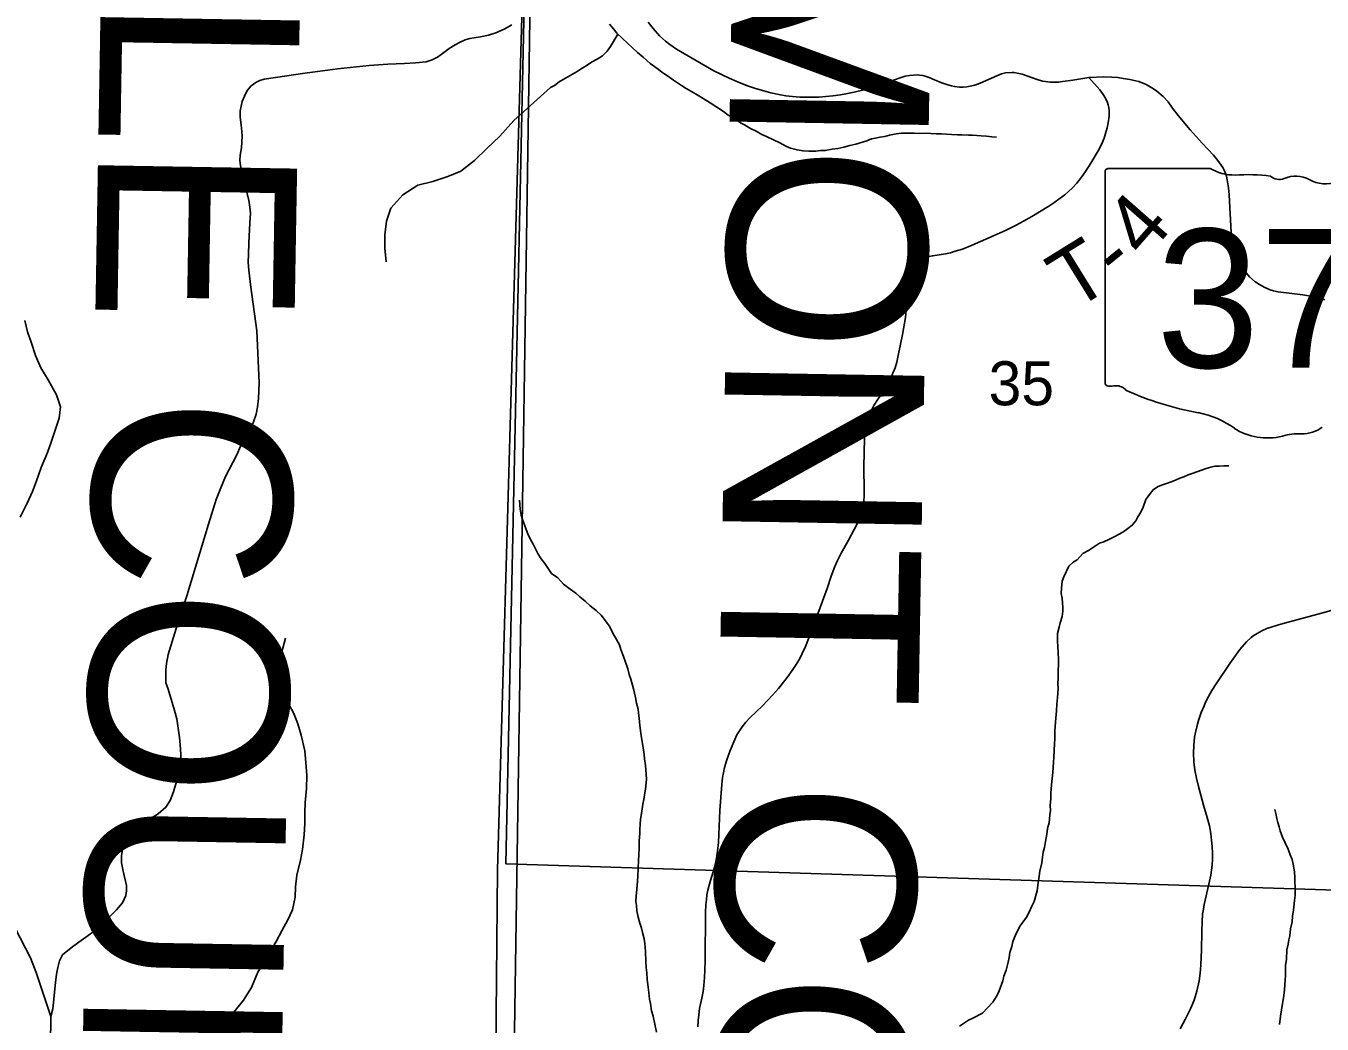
# Model space of a CAD drawing. Extents: x 0 to 34, y 0 to 22.
# Drawn here: x 26.601 to 27.832, y 18.434 to 19.383 of the extents above; entities that cross this region are included whole.
import ezdxf

# ---------------------------------------------------------------- set-up
doc = ezdxf.new("R2010")
doc.units = 0
for name, color, linetype in [('GM_X_Corporation', 7, 'Continuous'), ('GM_X_County', 7, 'Continuous'), ('GM_X_County_Text', 7, 'Continuous'), ('GM_X_Minor_River', 7, 'Continuous'), ('GM_X_Section_Text', 7, 'Continuous'), ('GM_X_State_Route', 7, 'Continuous'), ('GM_X_State_Shield', 7, 'Continuous'), ('GM_X_Township_Road', 7, 'Continuous'), ('GM_X_Township_Road_Text', 7, 'Continuous')]:
    doc.layers.add(name, color=color, linetype=linetype)

msp = doc.modelspace()

# ---------------------------------------------------------------- linework, layer by layer
at = {"layer": 'GM_X_Corporation'}
for points in [[(30.3167, 20.9), (27.1022, 20.9), (27.0898, 20.417), (27.0897, 20.4135), (27.089, 20.3692), (27.0873, 20.2665), (27.0907, 20.123), (27.0885, 20.1139), (27.0864, 20.0138), (27.0761, 19.6806), (27.0733, 19.498), (27.0719, 19.3912), (27.0487, 18.5805), (27.0419, 17.8236), (27.0349, 17.5522), (27.0234, 16.6611), (27.0124, 14.988), (27.0057, 14.5136), (27.2999, 14.5107), (27.8031, 14.5091), (28.4032, 14.497)], [(29.5503, 20.3788), (27.6751, 20.4106), (27.5829, 20.4116), (27.2336, 20.4152), (27.1239, 20.4163), (27.0898, 20.417), (27.0897, 20.4135), (27.089, 20.3692), (27.0873, 20.2665), (27.0907, 20.123), (27.0885, 20.1139), (27.0864, 20.0138), (27.0761, 19.6806), (27.0733, 19.498), (27.0719, 19.3912), (27.0487, 18.5805), (27.0419, 17.8236), (27.0349, 17.5522), (27.0234, 16.6611), (27.0124, 14.988), (27.0057, 14.5136), (27.2999, 14.5107), (27.8031, 14.5091), (28.4032, 14.497)], [(27.0234, 16.6611), (27.0349, 17.5522), (27.0419, 17.8236), (27.0487, 18.5805), (27.0719, 19.3912), (27.0733, 19.498), (27.0761, 19.6806), (27.0864, 20.0138), (27.0885, 20.1139), (27.0907, 20.123), (27.0873, 20.2665), (27.0031, 20.2673), (26.7822, 20.2704), (26.7196, 20.2707), (26.6351, 20.2734), (26.5702, 20.276), (26.2533, 20.2773), (25.4507, 20.2949), (24.5249, 20.3107), (24.0688, 20.3165), (24.0328, 20.3169), (23.5167, 20.3276), (23.5167, 14.5642)], [(27.0234, 16.6611), (27.0349, 17.5522), (27.0419, 17.8236), (27.0487, 18.5805), (27.0719, 19.3912), (27.0733, 19.498), (27.0761, 19.6806), (27.0864, 20.0138), (27.0885, 20.1139), (27.0907, 20.123), (27.0873, 20.2665), (27.0031, 20.2673), (26.7822, 20.2704), (26.7196, 20.2707), (26.6351, 20.2734), (26.5702, 20.276), (26.2533, 20.2773), (25.4507, 20.2949), (24.5249, 20.3107), (24.0688, 20.3165), (24.0328, 20.3169), (23.5167, 20.3276), (23.5167, 14.5642)]]:
    msp.add_lwpolyline(points, dxfattribs=at)
msp.add_lwpolyline([(27.9077, 19.5783), (27.8861, 18.5601), (27.0567, 18.5863), (27.0782, 19.5962)], close=True, dxfattribs=at)
at = {"layer": 'GM_X_County'}
msp.add_line((27.1022, 20.9), (27.0057, 14.5136), dxfattribs=at)
at = {"layer": 'GM_X_Minor_River'}
for points in [[(27.1553, 19.3845), (27.1591, 19.38), (27.1622, 19.3759), (27.1676, 19.371), (27.1769, 19.3621), (27.1819, 19.3576), (27.1872, 19.3531), (27.1938, 19.3472), (27.198, 19.3442), (27.2057, 19.3383), (27.2103, 19.3353), (27.216, 19.3313), (27.2198, 19.3287), (27.2237, 19.3261), (27.2279, 19.3235), (27.2332, 19.3206), (27.2401, 19.3165), (27.2443, 19.3139), (27.2508, 19.3099), (27.2635, 19.3014), (27.2681, 19.298), (27.2727, 19.2954), (27.2796, 19.2906), (27.2834, 19.2888), (27.2891, 19.2855), (27.2944, 19.2829), (27.2998, 19.2796), (27.3044, 19.2778), (27.3109, 19.2745), (27.317, 19.2716), (27.3235, 19.2683), (27.3273, 19.2668), (27.3334, 19.265), (27.3391, 19.264), (27.3447, 19.2637), (27.3512, 19.2638), (27.3557, 19.2643), (27.3602, 19.2643), (27.3667, 19.2656), (27.3723, 19.2665), (27.378, 19.2677), (27.3836, 19.2693), (27.3893, 19.2706), (27.3998, 19.2738), (27.4043, 19.2754), (27.4081, 19.2762), (27.4122, 19.277), (27.4168, 19.2779), (27.4213, 19.2791), (27.4277, 19.2803), (27.4326, 19.2808), (27.4447, 19.281), (27.4485, 19.2807), (27.4564, 19.2808), (27.4606, 19.2805), (27.4659, 19.2803), (27.4708, 19.2803), (27.4803, 19.2797)], [(27.163, 19.3752), (27.156, 19.3632), (27.1531, 19.359), (27.1486, 19.3544), (27.1434, 19.3512), (27.1381, 19.3485), (27.1329, 19.345), (27.1284, 19.3422), (27.1243, 19.3395), (27.1112, 19.3321), (27.1074, 19.3297), (27.103, 19.3262), (27.0992, 19.3243), (27.0643, 19.293)], [(27.0643, 19.293), (27.0508, 19.278), (27.0385, 19.2665), (27.0269, 19.255), (27.0138, 19.2449), (27.0014, 19.2398), (26.9874, 19.2351), (26.9731, 19.2315), (26.9589, 19.2222), (26.9473, 19.2096), (26.9433, 19.1974), (26.9416, 19.1844), (26.9417, 19.1715), (26.943, 19.1586)], [(27.4803, 19.2797), (27.486, 19.2795), (27.4901, 19.2792), (27.4962, 19.2789), (27.5, 19.279), (27.5083, 19.2783), (27.5133, 19.2781), (27.5186, 19.2774), (27.5231, 19.2771)], [(26.5951, 18.9159), (26.6018, 18.9293), (26.6069, 18.9403), (26.6106, 18.9503), (26.615, 18.9632), (26.6212, 18.9773), (26.6245, 18.9873), (26.6281, 18.9975), (26.6321, 19.0101), (26.6335, 19.0208), (26.6296, 19.0321), (26.6218, 19.0464), (26.6149, 19.0577), (26.6098, 19.0694), (26.6055, 19.0823), (26.602, 19.0921), (26.5996, 19.1027)], [(27.7436, 18.9648), (27.739, 18.9648), (27.7345, 18.9643), (27.7303, 18.9642), (27.7266, 18.9634), (27.7221, 18.9622), (27.7179, 18.9606), (27.7089, 18.9574), (27.7051, 18.9562), (27.701, 18.9542), (27.6972, 18.953), (27.6931, 18.9511), (27.689, 18.9495), (27.6845, 18.9479), (27.6796, 18.9463), (27.6758, 18.9447), (27.6717, 18.9419), (27.6684, 18.9373), (27.6647, 18.9327), (27.6622, 18.9255), (27.66, 18.9205), (27.6574, 18.9163), (27.6552, 18.9124), (27.6519, 18.9082), (27.6478, 18.9051), (27.6429, 18.9016), (27.6347, 18.8973), (27.6298, 18.8945), (27.6249, 18.8925), (27.6208, 18.891), (27.6152, 18.8874), (27.6103, 18.8843), (27.6051, 18.8812), (27.5995, 18.8754), (27.5957, 18.8731), (27.5916, 18.8692), (27.5869, 18.8592), (27.5855, 18.855), (27.5848, 18.8482), (27.5845, 18.8433), (27.5854, 18.8387), (27.5858, 18.8342), (27.5859, 18.8304), (27.586, 18.8266), (27.5853, 18.8213), (27.5835, 18.8155), (27.5824, 18.8113), (27.581, 18.8053), (27.5808, 18.7977), (27.5813, 18.7931), (27.5814, 18.7867), (27.5819, 18.781), (27.5819, 18.7764), (27.5817, 18.7692), (27.5814, 18.7631), (27.5811, 18.7578), (27.5816, 18.7529), (27.581, 18.7445), (27.5803, 18.7381), (27.5801, 18.7316), (27.5794, 18.7248), (27.5791, 18.721), (27.5785, 18.7126), (27.5783, 18.7047), (27.578, 18.7005), (27.5777, 18.6944), (27.5775, 18.6872), (27.5771, 18.6834), (27.5769, 18.6777), (27.5766, 18.6731), (27.5756, 18.6644), (27.575, 18.6576), (27.5747, 18.653), (27.5747, 18.6484), (27.5741, 18.6416), (27.5742, 18.6371), (27.5735, 18.6329), (27.5729, 18.6253), (27.5715, 18.6199), (27.5708, 18.6146), (27.5694, 18.6074), (27.5684, 18.6017), (27.5673, 18.5975), (27.5666, 18.5925), (27.566, 18.5872), (27.5642, 18.5792), (27.5635, 18.5746), (27.5622, 18.5659), (27.5615, 18.5606), (27.5587, 18.5503), (27.5561, 18.5453), (27.5539, 18.5403), (27.5514, 18.5357), (27.5484, 18.5311), (27.5451, 18.5269), (27.5411, 18.5185), (27.5385, 18.5124), (27.5375, 18.5078), (27.5357, 18.5021), (27.535, 18.4971), (27.534, 18.4929)], [(27.0695, 18.9321), (27.0704, 18.9233), (27.0713, 18.9177), (27.0725, 18.9135), (27.0744, 18.9086), (27.076, 18.9041), (27.0776, 18.8999), (27.08, 18.8947), (27.0827, 18.8902), (27.0855, 18.8845), (27.0874, 18.8808), (27.0902, 18.8763), (27.0936, 18.8718), (27.0968, 18.8669), (27.1002, 18.8624), (27.106, 18.8583), (27.1114, 18.8523), (27.1179, 18.8475), (27.1233, 18.8435), (27.1271, 18.8401), (27.1321, 18.836), (27.1367, 18.8315), (27.1425, 18.8271), (27.1471, 18.8226), (27.1552, 18.8121), (27.1584, 18.8057), (27.1619, 18.7994), (27.1646, 18.7945), (27.1658, 18.7899), (27.1686, 18.7835), (27.1702, 18.779), (27.1726, 18.7718), (27.1738, 18.7662), (27.1754, 18.7617), (27.1779, 18.7526), (27.1799, 18.7443), (27.1807, 18.739), (27.1824, 18.7333), (27.1828, 18.7295), (27.1833, 18.7246), (27.1841, 18.7178), (27.185, 18.7106), (27.1855, 18.7061), (27.1868, 18.6989), (27.188, 18.6902), (27.1885, 18.686), (27.1894, 18.6796), (27.1903, 18.6671), (27.19, 18.6633), (27.1894, 18.6572), (27.1883, 18.6519), (27.1877, 18.6473), (27.187, 18.6431), (27.1856, 18.634), (27.1846, 18.6286), (27.1843, 18.6241), (27.184, 18.6188), (27.1841, 18.615), (27.1834, 18.6081), (27.1835, 18.6017), (27.1829, 18.5941), (27.1826, 18.5899), (27.1824, 18.5816), (27.1821, 18.5747), (27.1818, 18.5698), (27.1812, 18.5618), (27.1806, 18.5557), (27.1803, 18.5504), (27.1807, 18.5466), (27.1812, 18.5417), (27.1824, 18.5357), (27.1841, 18.53), (27.1857, 18.5251), (27.1865, 18.5209), (27.1881, 18.5149), (27.1886, 18.5104), (27.1895, 18.5028), (27.1896, 18.4933), (27.1901, 18.4876), (27.1906, 18.4827), (27.1911, 18.4763), (27.1915, 18.4717), (27.1924, 18.4638), (27.1933, 18.4577), (27.1941, 18.4536), (27.195, 18.4464), (27.1966, 18.4415), (27.1999, 18.4263)], [(26.7869, 18.4339), (26.797, 18.4438), (26.8075, 18.4565), (26.8149, 18.4687), (26.8211, 18.4832), (26.8304, 18.4989), (26.8381, 18.5119), (26.8441, 18.5233), (26.8496, 18.5329), (26.854, 18.5424), (26.8565, 18.5546), (26.8568, 18.5645), (26.8582, 18.5755), (26.8614, 18.5899), (26.8635, 18.5998), (26.8649, 18.6139), (26.8655, 18.6245), (26.8657, 18.6348), (26.866, 18.6446), (26.8673, 18.6579), (26.8675, 18.6701), (26.8666, 18.6826), (26.8657, 18.6936), (26.8621, 18.7087), (26.859, 18.7193), (26.8551, 18.7291), (26.8485, 18.7415), (26.8442, 18.7551), (26.8421, 18.7688), (26.842, 18.7783), (26.8448, 18.7912), (26.8474, 18.8007)], [(27.7876, 18.6378), (27.7884, 18.634), (27.7892, 18.6295), (27.7904, 18.6257), (27.7916, 18.6216), (27.7925, 18.6178), (27.7948, 18.6117), (27.7972, 18.6061), (27.8, 18.6001), (27.802, 18.5948), (27.8039, 18.5903), (27.8048, 18.5861), (27.806, 18.5786), (27.8065, 18.5733), (27.8066, 18.5691), (27.8067, 18.5642), (27.8068, 18.5566), (27.8061, 18.5513), (27.8051, 18.5421), (27.8041, 18.5364), (27.8038, 18.5311), (27.8024, 18.5246), (27.8018, 18.5178), (27.8007, 18.514), (27.8, 18.5098), (27.799, 18.5045), (27.7984, 18.4957), (27.7977, 18.4896), (27.7975, 18.484), (27.7975, 18.4798), (27.7972, 18.476), (27.7966, 18.4665), (27.796, 18.4612), (27.7939, 18.4475), (27.7929, 18.4414), (27.7919, 18.4334)], [(27.534, 18.4929), (27.5322, 18.4853), (27.53, 18.4796), (27.529, 18.475), (27.5254, 18.4655), (27.5232, 18.4609), (27.5195, 18.4548), (27.5095, 18.4443), (27.5005, 18.4396), (27.4963, 18.4377), (27.4915, 18.4345), (27.4877, 18.4318)]]:
    msp.add_lwpolyline(points, dxfattribs=at)
at = {"layer": 'GM_X_State_Route'}
for points in [[(27.8351, 19.1224), (27.8291, 19.1244), (27.8252, 19.1253), (27.8141, 19.1271), (27.7906, 19.13), (27.7863, 19.131), (27.7831, 19.132), (27.7781, 19.1341), (27.7729, 19.1369), (27.7689, 19.1397), (27.7635, 19.1444), (27.7593, 19.1494), (27.7565, 19.1532), (27.7547, 19.1562), (27.7529, 19.1598), (27.7512, 19.1635), (27.7495, 19.1683), (27.7482, 19.1726), (27.7474, 19.1761), (27.7466, 19.1804), (27.7459, 19.1866), (27.7441, 19.2222), (27.7434, 19.2288), (27.7423, 19.2366), (27.7415, 19.2402), (27.7403, 19.2435), (27.7392, 19.2459), (27.7379, 19.2482), (27.7364, 19.2505), (27.7332, 19.2549), (27.7291, 19.2599), (27.7183, 19.2715), (27.7071, 19.2841), (27.6957, 19.2978), (27.6903, 19.3047), (27.686, 19.3107), (27.6812, 19.3159), (27.6752, 19.3209), (27.6722, 19.323), (27.669, 19.325), (27.6652, 19.3272), (27.6582, 19.3299), (27.6495, 19.3319), (27.6434, 19.333), (27.6381, 19.3337), (27.6327, 19.3342), (27.6251, 19.3346), (27.6107, 19.3338), (27.5956, 19.3314), (27.5858, 19.3299), (27.5819, 19.3295), (27.5793, 19.3294), (27.5741, 19.3295), (27.5694, 19.3301), (27.5667, 19.3305), (27.5615, 19.3318), (27.5474, 19.3369), (27.5425, 19.3381), (27.5397, 19.3385), (27.5377, 19.3386), (27.5316, 19.3382), (27.5278, 19.3373), (27.5232, 19.3355), (27.5075, 19.3286), (27.5023, 19.3267), (27.4979, 19.3256), (27.4946, 19.3251), (27.4912, 19.3248), (27.4879, 19.3247), (27.4831, 19.3253), (27.4801, 19.3259), (27.4766, 19.3269), (27.4702, 19.3291), (27.4641, 19.3316), (27.459, 19.3338), (27.455, 19.3351), (27.453, 19.3356), (27.4499, 19.3361), (27.4474, 19.3363), (27.4403, 19.3359), (27.4363, 19.335), (27.4063, 19.3249), (27.4026, 19.3238), (27.397, 19.3221), (27.3876, 19.3198), (27.3797, 19.3183), (27.3748, 19.3175), (27.3675, 19.3165), (27.354, 19.3153), (27.3457, 19.315), (27.3362, 19.3153), (27.329, 19.3158), (27.3228, 19.3165), (27.316, 19.3177), (27.3085, 19.3193), (27.3017, 19.3211), (27.294, 19.3234), (27.2864, 19.3259), (27.2762, 19.3299), (27.2688, 19.3331), (27.2615, 19.3366), (27.2544, 19.3403), (27.2363, 19.3507), (27.219, 19.3608), (27.2124, 19.3652), (27.2084, 19.3684), (27.2026, 19.3735), (27.1966, 19.3803), (27.1919, 19.3866)], [(27.6975, 18.4293), (27.7023, 18.4382), (27.7073, 18.4483), (27.7107, 18.4568), (27.7134, 18.4651), (27.7155, 18.4749), (27.7165, 18.4824), (27.7171, 18.4899), (27.7173, 18.4978), (27.7176, 18.5038), (27.7181, 18.5221), (27.7183, 18.5311), (27.7188, 18.5385), (27.7195, 18.5433), (27.7203, 18.5475), (27.7248, 18.5668), (27.7265, 18.5754), (27.7278, 18.5851), (27.7281, 18.5906), (27.7282, 18.5965), (27.7279, 18.6027), (27.7274, 18.6089), (27.7265, 18.6151), (27.7252, 18.6223), (27.7232, 18.6302), (27.7198, 18.642), (27.7148, 18.6598), (27.713, 18.6676), (27.7115, 18.6754), (27.7105, 18.6833), (27.7101, 18.6916), (27.7104, 18.6989), (27.7112, 18.7068), (27.712, 18.7111), (27.7132, 18.7164), (27.7148, 18.7224), (27.7161, 18.7264), (27.7175, 18.7303), (27.7202, 18.7366), (27.7217, 18.74), (27.7245, 18.7455), (27.7276, 18.751), (27.731, 18.7563), (27.7448, 18.7767), (27.7541, 18.7899), (27.7605, 18.7972), (27.7651, 18.8015), (27.7668, 18.8029), (27.7707, 18.8054), (27.7751, 18.8077), (27.7799, 18.8099), (27.7848, 18.8116), (27.7933, 18.8141), (27.8318, 18.8247), (27.8767, 18.8371)]]:
    msp.add_lwpolyline(points, dxfattribs=at)
at = {"layer": 'GM_X_State_Shield'}
for p, q in [((27.6263, 19.244), (27.6263, 19.0439)), ((27.726, 19.2474), (27.6295, 19.2474))]:
    msp.add_line(p, q, dxfattribs=at)
for centre, major_axis, start_param, end_param in [((27.63, 19.2444), (0.00382, 0), 1.712693, 3.28349), ((27.749, 19.2707), (0.037, 0), 4.042523, 4.731795), ((27.7613, 19.1351), (0.133, 0), 1.404758, 1.657858), ((27.7915, 19.2455), (0.0107, 0), 3.836095, 5.185415), ((27.8072, 19.2223), (0.0222, 0), 0.950623, 2.079405), ((27.8358, 19.2541), (0.0267, 0), 4.081561, 5.145723), ((27.6301, 19.0434), (0.00385, 0), 3.00124, 4.508301), ((27.6307, 19.0639), (0.0294, 0), 4.665946, 4.897461), ((27.6367, 19.0323), (0.0106, 0), 0.519207, 1.627899), ((27.7705, 19.2121), (0.2524, 0), 4.195997, 4.488961), ((27.6953, 18.954), (0.079, 0), 0.823519, 1.323587), ((27.7807, 19.0313), (0.0501, 0), 4.026481, 4.996735), ((27.8096, 18.9622), (0.0412, 0), 1.495662, 1.94098), ((27.8133, 19.0164), (0.0267, 0), 4.691044, 5.507374)]:
    msp.add_ellipse(centre, major_axis=major_axis, ratio=0.8, start_param=start_param, end_param=end_param, dxfattribs=at)
at = {"layer": 'GM_X_Township_Road'}
for points in [[(26.6243, 18.4411), (26.6262, 18.4483), (26.6286, 18.4733), (26.6297, 18.4814), (26.6309, 18.4876), (26.6324, 18.494), (26.6352, 18.4997), (26.6453, 18.5076), (26.6653, 18.5224), (26.6799, 18.5359), (26.6867, 18.5425), (26.6924, 18.5492), (26.6954, 18.5561), (26.6962, 18.5606), (26.6963, 18.5658), (26.6931, 18.5792), (26.6913, 18.5873), (26.6913, 18.594), (26.6923, 18.5998), (26.6932, 18.6054), (26.6987, 18.6148), (26.7041, 18.6195), (26.7093, 18.6235), (26.7142, 18.6266), (26.7194, 18.6293), (26.7262, 18.6338), (26.7336, 18.6401), (26.7377, 18.6466), (26.7409, 18.6547), (26.7438, 18.6647), (26.7468, 18.6778), (26.7476, 18.6841), (26.7478, 18.6896), (26.7476, 18.6955), (26.7464, 18.7065), (26.744, 18.724), (26.7418, 18.7321), (26.7385, 18.7428), (26.7354, 18.7534), (26.7337, 18.7582), (26.7334, 18.7642), (26.7334, 18.7706), (26.7342, 18.7766), (26.7359, 18.7853), (26.7471, 18.8224), (26.7535, 18.8412), (26.774, 18.9092), (26.7815, 18.9326), (26.7859, 18.9436), (26.7904, 18.9545), (26.8011, 18.975), (26.8045, 18.9832), (26.8106, 18.9945), (26.8135, 18.9993), (26.8165, 19.0054), (26.8193, 19.0139), (26.8207, 19.0203), (26.8217, 19.0287), (26.8222, 19.0436), (26.8201, 19.093), (26.8144, 19.1344), (26.8123, 19.1507), (26.8118, 19.158), (26.812, 19.1659), (26.8123, 19.1764), (26.8135, 19.1956), (26.814, 19.2048), (26.8135, 19.2106), (26.8125, 19.2173), (26.8059, 19.2436), (26.8044, 19.2502), (26.804, 19.2549), (26.8043, 19.2599), (26.8056, 19.267), (26.8061, 19.278), (26.8059, 19.2826), (26.8052, 19.289), (26.8041, 19.2962), (26.8042, 19.3023), (26.8062, 19.311), (26.8082, 19.3161), (26.8095, 19.3189), (26.8111, 19.3217), (26.8147, 19.326), (26.819, 19.3292), (26.8228, 19.331), (26.8269, 19.3322), (26.8485, 19.3354), (26.8634, 19.3378), (26.8966, 19.342), (26.9269, 19.3452), (26.9446, 19.3464), (26.9603, 19.3471), (26.9707, 19.3477), (26.9809, 19.3488), (26.9838, 19.3496), (26.9868, 19.3507), (26.9916, 19.3533), (26.9951, 19.3556), (27.0029, 19.3615), (27.0084, 19.3648), (27.0125, 19.3672), (27.0181, 19.3697), (27.0224, 19.371), (27.0266, 19.3717), (27.0327, 19.3726), (27.0401, 19.3741), (27.0472, 19.3763), (27.055, 19.3798), (27.0624, 19.3839)], [(27.2392, 18.4313), (27.2395, 18.4374), (27.24, 18.4427), (27.2407, 18.4487), (27.2428, 18.4585), (27.2442, 18.465), (27.2448, 18.4706), (27.2455, 18.4782), (27.2458, 18.4851), (27.246, 18.4941), (27.2463, 18.5404), (27.2467, 18.5472), (27.2472, 18.5524), (27.2477, 18.5567), (27.2486, 18.5612), (27.2511, 18.5705), (27.2537, 18.5786), (27.2552, 18.5842), (27.2567, 18.5918), (27.2578, 18.5982), (27.2586, 18.6066), (27.26, 18.6369), (27.262, 18.6618), (27.2627, 18.6683), (27.2634, 18.6729), (27.2642, 18.6766), (27.2653, 18.6809), (27.2667, 18.6851), (27.27, 18.694), (27.2753, 18.7067), (27.2763, 18.7088), (27.278, 18.7117), (27.2812, 18.7165), (27.2847, 18.721), (27.2885, 18.7251), (27.3005, 18.7365), (27.3102, 18.7467), (27.3158, 18.7531), (27.3206, 18.7591), (27.3239, 18.7634), (27.3294, 18.7711), (27.3326, 18.7759), (27.336, 18.7814), (27.3384, 18.7863), (27.3414, 18.7929), (27.3472, 18.8075), (27.3532, 18.8238), (27.3619, 18.848), (27.3658, 18.8599), (27.3694, 18.8689), (27.3719, 18.8746), (27.375, 18.881), (27.3824, 18.894), (27.3877, 18.904), (27.3902, 18.909), (27.392, 18.9131), (27.3939, 18.9187), (27.3951, 18.9231), (27.3962, 18.9278), (27.3968, 18.9313), (27.3972, 18.9358), (27.3973, 18.9405), (27.397, 18.9638), (27.3974, 18.9909), (27.3979, 18.9952), (27.3989, 19.002), (27.3997, 19.0054), (27.401, 19.0099), (27.4024, 19.0138), (27.4038, 19.017), (27.4065, 19.0221), (27.4106, 19.0284), (27.4164, 19.0369), (27.418, 19.0398), (27.4205, 19.044), (27.423, 19.0491), (27.4245, 19.0526), (27.4265, 19.0578), (27.4281, 19.0631), (27.4296, 19.0697), (27.4335, 19.0894), (27.4364, 19.1056), (27.4372, 19.1125), (27.4378, 19.1213), (27.438, 19.1271), (27.4383, 19.1455), (27.4389, 19.1479), (27.4398, 19.1504), (27.4412, 19.1532), (27.4442, 19.1573), (27.4463, 19.1592), (27.4483, 19.1603), (27.4503, 19.1614), (27.452, 19.1621), (27.4543, 19.1629), (27.4623, 19.1644), (27.4744, 19.1662), (27.4791, 19.1673), (27.4838, 19.1686), (27.4905, 19.1708), (27.4999, 19.1746), (27.5208, 19.1837), (27.5321, 19.1888), (27.5416, 19.1936), (27.5485, 19.1972), (27.5565, 19.2018), (27.5728, 19.2116), (27.5775, 19.2147), (27.5835, 19.219), (27.5879, 19.2224), (27.5951, 19.2289), (27.5994, 19.2335), (27.6015, 19.2361), (27.6038, 19.2391), (27.6076, 19.2444), (27.6126, 19.2523), (27.6196, 19.2641), (27.6227, 19.27), (27.6252, 19.2762), (27.6273, 19.2827), (27.6281, 19.2859), (27.6291, 19.2907), (27.63, 19.2971), (27.6301, 19.2992), (27.6299, 19.3023), (27.6296, 19.3054), (27.629, 19.3079), (27.6283, 19.31), (27.6264, 19.3143), (27.6244, 19.3176), (27.621, 19.3221), (27.6107, 19.3338)], [(26.5905, 18.525), (26.6049, 18.497), (26.6103, 18.4829), (26.6197, 18.4544), (26.6243, 18.4411)], [(26.6236, 18.3872), (26.6243, 18.4411)]]:
    msp.add_lwpolyline(points, dxfattribs=at)

# ---------------------------------------------------------------- texts
at = {"layer": 'GM_X_County_Text'}
for s, rotation, p in [('NOBLE COUNTY', 269.0214, (26.6811, 19.9608)), ('BELMONT COUNTY', 268.998, (27.2809, 19.9608))]:
    msp.add_text(s, height=0.189394, rotation=rotation, dxfattribs=at).set_placement(p)
at = {"layer": 'GM_X_Section_Text'}
msp.add_text('35', height=0.04186, rotation=0, dxfattribs=at).set_placement((27.5154, 19.0222))
at = {"layer": 'GM_X_State_Shield'}
msp.add_text('379', height=0.13184, dxfattribs=at).set_placement((27.6747, 19.058))
at = {"layer": 'GM_X_Township_Road_Text'}
for s, rotation, p in [('4', 48.7838, (27.6639, 19.1602)), ('T', 31.7333, (27.5957, 19.1112)), ('-', 39.033, (27.6382, 19.1382))]:
    msp.add_text(s, height=0.0568, rotation=rotation, dxfattribs=at).set_placement(p)

doc.saveas('drawing.dxf')
